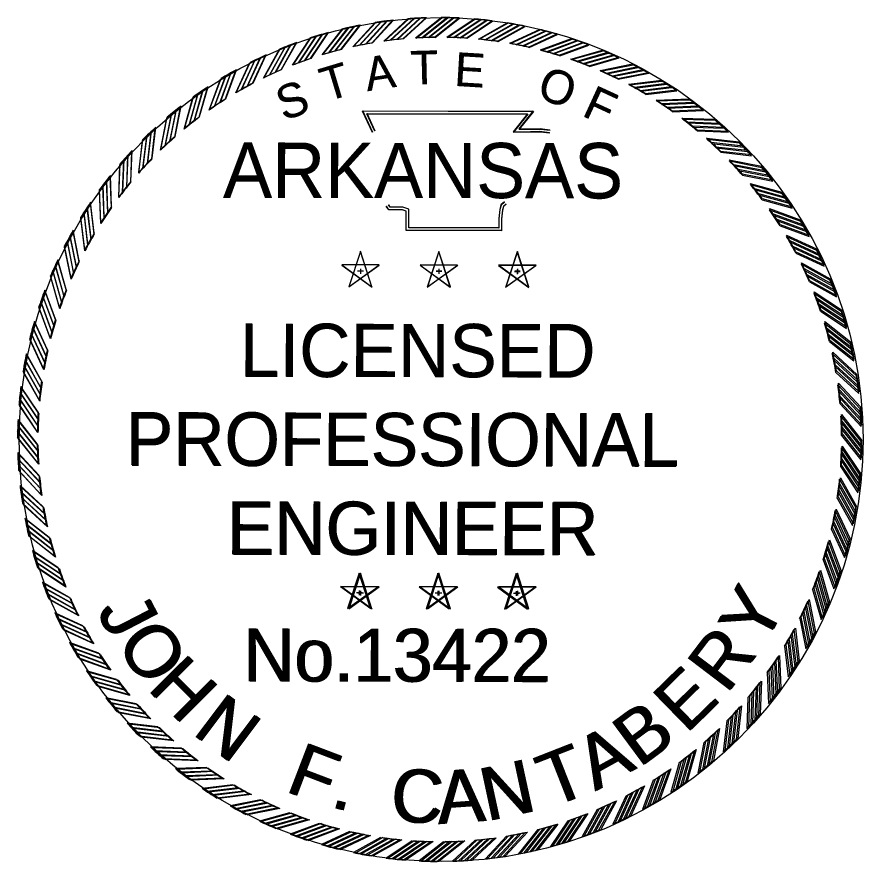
# Model space of a CAD drawing. Extents: x 0 to 762217, y -63 to 1662473.
# Drawn here: x 1782.1 to 1902.4, y 771.5 to 891.6 of the extents above; entities that cross this region are included whole.
import ezdxf

# ---------------------------------------------------------------- set-up
doc = ezdxf.new("R2010")
doc.units = 0
for name, color, linetype in [('Default', 7, 'Continuous'), ('G-ANNO-SYMB', 7, 'Continuous'), ('G-ANNO-TEXT', 7, 'Continuous'), ('G-No Plot-Stamp', 7, 'Continuous')]:
    doc.layers.add(name, color=color, linetype=linetype)

# ---------------------------------------------------------------- blocks, each defined once
blk = doc.blocks.new('STAR')
at = {"layer": 'Default'}
for p, q in [((-0.0001, 0.0615), (-0.0366, -0.0504)), ((0.0362, -0.0503), (0, 0.0617)), ((0.0587, 0.0188), (-0.059, 0.0189)), ((-0.0589, 0.0188), (0.0363, -0.0505)), ((-0.0365, -0.0503), (0.0589, 0.0188)), ((-0.0085, 0), (0.009, 0)), ((0, 0.0063), (0, -0.0085))]:
    blk.add_line(p, q, dxfattribs=at)
blk = doc.blocks.new('RP')
at = {"layer": 'Default'}
for p, q in [((-0.0781, 1.2656), (0.003, 1.33)), ((-0.058, 1.2667), (0.0216, 1.3299)), ((-0.0375, 1.2674), (0.0405, 1.3294)), ((-0.0176, 1.2679), (0.059, 1.3287))]:
    blk.add_line(p, q, dxfattribs=at)
for radius, start, end in [(1.33, 87.4562, 89.8699), (1.268, 90.7933, 93.5307)]:
    blk.add_arc((0, 0), radius, start, end, dxfattribs=at)

msp = doc.modelspace()

# ---------------------------------------------------------------- linework, layer by layer
at = {"layer": 'G-ANNO-SYMB'}
for points in [[(1832.61, 875.21), (1831.2, 878.24), (1855.46, 878.26), (1853.44, 875.71), (1855.09, 875.73), (1856.46, 875.75), (1857.84, 875.6)], [(1832.65, 875.22), (1831.26, 878.27), (1855.52, 878.2), (1853.49, 875.66), (1855.13, 875.67), (1856.51, 875.69), (1857.89, 875.53)], [(1832.96, 875.37), (1831.81, 877.86), (1854.67, 877.87), (1852.63, 875.32), (1855.09, 875.35), (1856.44, 875.37), (1857.8, 875.22)], [(1833, 875.38), (1831.86, 877.88), (1854.72, 877.81), (1852.68, 875.26), (1855.14, 875.29), (1856.49, 875.3), (1857.84, 875.15)], [(1851.4, 865.34), (1850.89, 864.92), (1850.71, 864.27), (1850.57, 862.96), (1850.57, 861.65), (1837.8, 861.65), (1837.8, 863.53), (1837.8, 864.32), (1836.92, 864.59), (1835.14, 864.59), (1834.91, 864.93)], [(1851.41, 865.29), (1850.9, 864.88), (1850.72, 864.23), (1850.57, 862.92), (1850.57, 861.61), (1837.8, 861.65), (1837.8, 863.53), (1837.81, 864.32), (1836.93, 864.59), (1835.15, 864.59), (1834.93, 864.94)], [(1851.64, 865.04), (1851.23, 864.7), (1851.09, 864.2), (1850.95, 862.94), (1850.95, 861.27), (1837.41, 861.27), (1837.41, 863.53), (1837.41, 864.03), (1836.86, 864.2), (1834.94, 864.2), (1834.59, 864.72)], [(1851.65, 864.99), (1851.24, 864.66), (1851.1, 864.15), (1850.96, 862.9), (1850.95, 861.22), (1837.41, 861.27), (1837.42, 863.53), (1837.42, 864.03), (1836.87, 864.2), (1834.95, 864.21), (1834.6, 864.73)]]:
    msp.add_lwpolyline(points, dxfattribs=at)
at = {"layer": 'G-No Plot-Stamp'}
msp.add_circle((1842.38, 831.54), 60, dxfattribs=at)

# ---------------------------------------------------------------- block references
at = {"layer": 'G-ANNO-SYMB'}
for name, p, xscale, yscale, rotation in [('RP', (1842.24, 831.56), 45.10357918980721, 45.10357918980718, 4.500000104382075), ('RP', (1842.24, 831.56), 45.103579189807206, 45.10357918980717, -4.499999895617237), ('RP', (1842.14, 831.54), 45.103579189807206, 45.10357918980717, -4.695800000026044), ('RP', (1842.24, 831.56), 45.10357918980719, 45.10357918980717, 13.500000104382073), ('RP', (1842.14, 831.54), 45.1035791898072, 45.103579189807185, 13.304199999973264), ('RP', (1842.24, 831.56), 45.103579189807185, 45.103579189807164, 9.000000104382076), ('RP', (1842.14, 831.54), 45.10357918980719, 45.103579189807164, 8.804199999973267), ('RP', (1842.14, 831.54), 45.1035791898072, 45.10357918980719, 4.304199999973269), ('RP', (1842.24, 831.56), 45.1035791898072, 45.10357918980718, 1.0438208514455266e-07), ('RP', (1842.14, 831.54), 45.1035791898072, 45.10357918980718, -0.19580000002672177), ('RP', (1842.24, 831.56), 45.10357918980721, 45.103579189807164, -8.999999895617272), ('RP', (1842.14, 831.54), 45.10357918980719, 45.103579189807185, -9.19580000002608), ('RP', (1842.24, 831.56), 45.10357918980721, 45.10357918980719, -13.499999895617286), ('RP', (1842.14, 831.54), 45.103579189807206, 45.103579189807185, -13.695800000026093), ('RP', (1842.24, 831.56), 45.103579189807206, 45.10357918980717, 18.00000010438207), ('RP', (1842.14, 831.54), 45.1035791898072, 45.10357918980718, 17.804199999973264), ('RP', (1842.24, 831.56), 45.103579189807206, 45.103579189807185, -17.999999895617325), ('RP', (1842.14, 831.54), 45.1035791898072, 45.10357918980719, -18.19580000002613), ('RP', (1842.24, 831.56), 45.1035791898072, 45.10357918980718, 22.500000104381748), ('RP', (1842.14, 831.54), 45.1035791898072, 45.10357918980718, 22.304199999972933), ('RP', (1842.24, 831.56), 45.103579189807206, 45.10357918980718, -22.499999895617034), ('RP', (1842.14, 831.54), 45.10357918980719, 45.103579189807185, -22.695800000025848), ('RP', (1842.24, 831.56), 45.1035791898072, 45.10357918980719, 27.000000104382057), ('RP', (1842.14, 831.54), 45.1035791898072, 45.103579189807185, 26.80419999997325), ('RP', (1842.24, 831.56), 45.10357918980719, 45.103579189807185, -26.999999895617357), ('RP', (1842.14, 831.54), 45.1035791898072, 45.10357918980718, -27.19580000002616), ('RP', (1842.24, 831.56), 45.10357918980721, 45.1035791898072, -31.49999989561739), ('RP', (1842.14, 831.54), 45.103579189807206, 45.1035791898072, -31.695800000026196), ('RP', (1842.24, 831.56), 45.10357918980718, 45.103579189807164, 31.50000010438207), ('RP', (1842.14, 831.54), 45.10357918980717, 45.103579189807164, 31.30419999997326), ('RP', (1842.24, 831.56), 45.10357918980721, 45.10357918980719, -35.999999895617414), ('RP', (1842.14, 831.54), 45.1035791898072, 45.10357918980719, -36.195800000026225), ('RP', (1842.24, 831.56), 45.10357918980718, 45.103579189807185, 36.00000010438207), ('RP', (1842.14, 831.54), 45.10357918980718, 45.10357918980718, 35.804199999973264), ('RP', (1842.24, 831.56), 45.103579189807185, 45.10357918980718, 40.50000010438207), ('RP', (1842.14, 831.54), 45.103579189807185, 45.10357918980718, 40.30419999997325), ('RP', (1842.24, 831.56), 45.1035791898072, 45.1035791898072, -40.49999989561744), ('RP', (1842.14, 831.54), 45.1035791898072, 45.10357918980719, -40.69580000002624), ('RP', (1842.14, 831.54), 45.103579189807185, 45.10357918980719, 44.80419999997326), ('RP', (1842.24, 831.56), 45.1035791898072, 45.10357918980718, -44.99999989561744), ('RP', (1842.14, 831.54), 45.103579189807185, 45.10357918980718, -45.19580000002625), ('RP', (1842.24, 831.56), 45.10357918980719, 45.10357918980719, 45.00000010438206), ('RP', (1842.24, 831.56), 45.10357918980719, 45.103579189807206, 49.500000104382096), ('RP', (1842.14, 831.54), 45.103579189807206, 45.1035791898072, 49.304199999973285), ('RP', (1842.24, 831.56), 45.103579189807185, 45.10357918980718, -49.499999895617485), ('RP', (1842.14, 831.54), 45.10357918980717, 45.103579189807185, -49.695800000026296), ('RP', (1842.24, 831.56), 45.103579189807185, 45.10357918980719, 54.00000010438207), ('RP', (1842.14, 831.54), 45.10357918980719, 45.103579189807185, 53.804199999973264), ('RP', (1842.24, 831.56), 45.10357918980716, 45.10357918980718, -53.999999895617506), ('RP', (1842.14, 831.54), 45.103579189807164, 45.10357918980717, -54.1958000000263), ('RP', (1842.14, 831.54), 45.10357918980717, 45.103579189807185, 58.304199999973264), ('RP', (1842.24, 831.56), 45.10357918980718, 45.10357918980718, 58.50000010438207), ('RP', (1842.24, 831.56), 45.103579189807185, 45.10357918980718, -58.49999989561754), ('RP', (1842.14, 831.54), 45.10357918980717, 45.103579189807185, -58.695800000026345), ('RP', (1842.24, 831.56), 45.10357918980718, 45.10357918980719, -62.99999989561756), ('RP', (1842.14, 831.54), 45.103579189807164, 45.10357918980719, -63.19580000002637), ('RP', (1842.14, 831.54), 45.103579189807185, 45.103579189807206, 62.804199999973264), ('RP', (1842.24, 831.56), 45.10357918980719, 45.1035791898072, 63.000000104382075), ('STAR', (1830.9, 855.53), 45.1035791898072, 45.10357918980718, -0.19580000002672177), ('STAR', (1830.92, 855.51), 45.1035791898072, 45.10357918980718, 1.0438208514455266e-07), ('STAR', (1842.06, 855.49), 45.1035791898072, 45.10357918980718, -0.19580000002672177), ('STAR', (1842.08, 855.51), 45.1035791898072, 45.10357918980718, 1.0438208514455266e-07), ('STAR', (1853.21, 855.45), 45.1035791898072, 45.10357918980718, -0.19580000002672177), ('STAR', (1853.23, 855.51), 45.1035791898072, 45.10357918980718, 1.0438208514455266e-07), ('RP', (1842.14, 831.54), 45.10357918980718, 45.1035791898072, 67.30419999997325), ('RP', (1842.24, 831.56), 45.10357918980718, 45.103579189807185, 67.50000010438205), ('RP', (1842.14, 831.54), 45.10357918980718, 45.103579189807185, -67.69580000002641), ('RP', (1842.24, 831.56), 45.10357918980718, 45.1035791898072, -67.49999989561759), ('RP', (1842.14, 831.54), 45.10357918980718, 45.1035791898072, -72.19580000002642), ('RP', (1842.24, 831.56), 45.10357918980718, 45.1035791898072, -71.99999989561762), ('RP', (1842.14, 831.54), 45.103579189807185, 45.1035791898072, 71.80419999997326), ('RP', (1842.24, 831.56), 45.103579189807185, 45.10357918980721, 72.00000010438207), ('RP', (1842.14, 831.54), 45.10357918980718, 45.1035791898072, 76.30419999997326), ('RP', (1842.14, 831.54), 45.10357918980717, 45.10357918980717, -76.69580000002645), ('RP', (1842.24, 831.56), 45.103579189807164, 45.10357918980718, -76.49999989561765), ('RP', (1842.24, 831.56), 45.103579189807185, 45.103579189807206, 76.50000010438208), ('RP', (1842.14, 831.54), 45.10357918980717, 45.10357918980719, 80.80419999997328), ('RP', (1842.24, 831.56), 45.10357918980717, 45.10357918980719, 81.0000001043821), ('RP', (1842.14, 831.54), 45.10357918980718, 45.1035791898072, -81.19580000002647), ('RP', (1842.24, 831.56), 45.10357918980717, 45.1035791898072, -80.99999989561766), ('RP', (1842.14, 831.54), 45.10357918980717, 45.10357918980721, 85.30419999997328), ('RP', (1842.24, 831.56), 45.10357918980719, 45.1035791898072, 85.50000010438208), ('RP', (1842.14, 831.54), 45.103579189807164, 45.10357918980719, -85.69580000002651), ('RP', (1842.24, 831.56), 45.10357918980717, 45.103579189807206, -85.49999989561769), ('RP', (1842.24, 831.56), 45.10357918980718, 45.10357918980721, -89.99999989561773), ('RP', (1842.14, 831.54), 45.10357918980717, 45.103579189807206, 89.80419999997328), ('RP', (1842.24, 831.56), 45.103579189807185, 45.10357918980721, 90.0000001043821), ('RP', (1842.14, 831.54), 45.10357918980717, 45.103579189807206, -90.19580000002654), ('RP', (1842.14, 831.54), 45.10357918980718, 45.103579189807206, -94.69580000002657), ('RP', (1842.24, 831.56), 45.103579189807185, 45.10357918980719, -94.49999989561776), ('RP', (1842.14, 831.54), 45.10357918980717, 45.10357918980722, 94.30419999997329), ('RP', (1842.24, 831.56), 45.103579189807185, 45.10357918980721, 94.5000001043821), ('RP', (1842.14, 831.54), 45.10357918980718, 45.10357918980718, 98.8041999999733), ('RP', (1842.14, 831.54), 45.10357918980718, 45.1035791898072, -99.19580000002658), ('RP', (1842.24, 831.56), 45.10357918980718, 45.1035791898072, -98.99999989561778), ('RP', (1842.24, 831.56), 45.10357918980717, 45.103579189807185, 99.0000001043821), ('RP', (1842.14, 831.54), 45.10357918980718, 45.1035791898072, 103.30419999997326), ('RP', (1842.24, 831.56), 45.10357918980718, 45.1035791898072, 103.50000010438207), ('RP', (1842.14, 831.54), 45.10357918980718, 45.1035791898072, -103.69580000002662), ('RP', (1842.24, 831.56), 45.10357918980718, 45.10357918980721, -103.49999989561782), ('RP', (1842.14, 831.54), 45.10357918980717, 45.1035791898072, -108.19580000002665), ('RP', (1842.24, 831.56), 45.10357918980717, 45.1035791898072, -107.99999989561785), ('RP', (1842.14, 831.54), 45.10357918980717, 45.10357918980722, 107.80419999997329), ('RP', (1842.24, 831.56), 45.10357918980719, 45.10357918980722, 108.0000001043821), ('RP', (1842.14, 831.54), 45.10357918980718, 45.103579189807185, 112.30419999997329), ('RP', (1842.24, 831.56), 45.10357918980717, 45.1035791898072, 112.5000001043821), ('STAR', (1830.74, 809.78), 45.1035791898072, 45.10357918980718, -0.19580000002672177), ('STAR', (1830.92, 809.76), 45.1035791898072, 45.10357918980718, 1.0438208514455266e-07), ('STAR', (1841.9, 809.74), 45.1035791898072, 45.10357918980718, -0.19580000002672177), ('STAR', (1842.08, 809.76), 45.1035791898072, 45.10357918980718, 1.0438208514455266e-07), ('STAR', (1853.06, 809.7), 45.1035791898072, 45.10357918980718, -0.19580000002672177), ('STAR', (1853.23, 809.76), 45.1035791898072, 45.10357918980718, 1.0438208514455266e-07), ('RP', (1842.14, 831.54), 45.10357918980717, 45.103579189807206, -112.69580000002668), ('RP', (1842.24, 831.56), 45.10357918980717, 45.10357918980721, -112.49999989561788), ('RP', (1842.14, 831.54), 45.10357918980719, 45.103579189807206, -117.19580000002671), ('RP', (1842.24, 831.56), 45.1035791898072, 45.103579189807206, -116.9999998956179), ('RP', (1842.14, 831.54), 45.103579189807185, 45.1035791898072, 116.80419999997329), ('RP', (1842.24, 831.56), 45.10357918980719, 45.1035791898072, 117.0000001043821), ('RP', (1842.14, 831.54), 45.103579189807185, 45.103579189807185, 121.30419999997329), ('RP', (1842.24, 831.56), 45.103579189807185, 45.10357918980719, 121.5000001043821), ('RP', (1842.14, 831.54), 45.10357918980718, 45.103579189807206, -121.69580000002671), ('RP', (1842.24, 831.56), 45.10357918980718, 45.103579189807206, -121.4999998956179), ('RP', (1842.14, 831.54), 45.10357918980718, 45.10357918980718, 125.80419999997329), ('RP', (1842.24, 831.56), 45.10357918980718, 45.103579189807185, 126.00000010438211), ('RP', (1842.14, 831.54), 45.10357918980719, 45.1035791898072, -126.19580000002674), ('RP', (1842.24, 831.56), 45.103579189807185, 45.103579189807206, -125.99999989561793), ('RP', (1842.14, 831.54), 45.10357918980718, 45.103579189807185, 130.3041999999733), ('RP', (1842.14, 831.54), 45.103579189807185, 45.10357918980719, -130.6958000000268), ('RP', (1842.24, 831.56), 45.103579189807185, 45.10357918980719, -130.49999989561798), ('RP', (1842.24, 831.56), 45.103579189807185, 45.10357918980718, 130.50000010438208), ('RP', (1842.14, 831.54), 45.10357918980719, 45.103579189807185, 134.80419999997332), ('RP', (1842.24, 831.56), 45.1035791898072, 45.103579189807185, 135.00000010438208), ('RP', (1842.14, 831.54), 45.103579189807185, 45.10357918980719, -135.19580000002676), ('RP', (1842.24, 831.56), 45.10357918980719, 45.10357918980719, -134.99999989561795), ('RP', (1842.14, 831.54), 45.10357918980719, 45.103579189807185, 139.30419999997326), ('RP', (1842.24, 831.56), 45.10357918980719, 45.103579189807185, 139.50000010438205), ('RP', (1842.14, 831.54), 45.10357918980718, 45.103579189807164, -139.69580000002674), ('RP', (1842.24, 831.56), 45.103579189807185, 45.10357918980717, -139.49999989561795), ('RP', (1842.14, 831.54), 45.103579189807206, 45.103579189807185, 143.8041999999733), ('RP', (1842.24, 831.56), 45.103579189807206, 45.103579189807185, 144.00000010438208), ('RP', (1842.14, 831.54), 45.103579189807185, 45.103579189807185, -144.19580000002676), ('RP', (1842.24, 831.56), 45.1035791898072, 45.10357918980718, -143.99999989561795), ('RP', (1842.14, 831.54), 45.10357918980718, 45.10357918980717, -148.69580000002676), ('RP', (1842.24, 831.56), 45.10357918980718, 45.103579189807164, -148.49999989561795), ('RP', (1842.14, 831.54), 45.10357918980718, 45.10357918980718, 148.3041999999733), ('RP', (1842.24, 831.56), 45.103579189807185, 45.10357918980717, 148.50000010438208), ('RP', (1842.14, 831.54), 45.103579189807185, 45.10357918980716, -153.1958000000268), ('RP', (1842.24, 831.56), 45.10357918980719, 45.103579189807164, -152.99999989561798), ('RP', (1842.14, 831.54), 45.10357918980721, 45.103579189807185, 152.8041999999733), ('RP', (1842.24, 831.56), 45.10357918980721, 45.1035791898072, 153.00000010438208), ('RP', (1842.14, 831.54), 45.1035791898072, 45.10357918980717, 157.3041999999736), ('RP', (1842.24, 831.56), 45.103579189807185, 45.10357918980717, 157.50000010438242), ('RP', (1842.14, 831.54), 45.1035791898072, 45.103579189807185, -157.6958000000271), ('RP', (1842.24, 831.56), 45.10357918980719, 45.10357918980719, -157.4999998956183), ('RP', (1842.14, 831.54), 45.103579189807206, 45.10357918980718, 161.8041999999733), ('RP', (1842.24, 831.56), 45.10357918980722, 45.103579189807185, 162.00000010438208), ('RP', (1842.14, 831.54), 45.1035791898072, 45.10357918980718, -162.19580000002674), ('RP', (1842.24, 831.56), 45.103579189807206, 45.103579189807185, -161.99999989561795), ('RP', (1842.14, 831.54), 45.103579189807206, 45.10357918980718, 166.3041999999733), ('RP', (1842.24, 831.56), 45.103579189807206, 45.10357918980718, 166.50000010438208), ('RP', (1842.14, 831.54), 45.1035791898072, 45.10357918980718, -166.69580000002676), ('RP', (1842.24, 831.56), 45.10357918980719, 45.103579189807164, -166.49999989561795), ('RP', (1842.14, 831.54), 45.1035791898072, 45.10357918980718, 170.8041999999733), ('RP', (1842.24, 831.56), 45.1035791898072, 45.10357918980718, 171.00000010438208), ('RP', (1842.14, 831.54), 45.103579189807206, 45.10357918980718, 175.3041999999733), ('RP', (1842.24, 831.56), 45.10357918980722, 45.10357918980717, 175.50000010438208), ('RP', (1842.14, 831.54), 45.10357918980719, 45.103579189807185, -175.69580000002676), ('RP', (1842.24, 831.56), 45.1035791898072, 45.10357918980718, -175.49999989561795), ('RP', (1842.14, 831.54), 45.10357918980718, 45.10357918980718, -171.19580000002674), ('RP', (1842.24, 831.56), 45.103579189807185, 45.103579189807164, -170.99999989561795), ('RP', (1842.14, 831.54), 45.1035791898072, 45.10357918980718, 179.8041999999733), ('RP', (1842.24, 831.56), 45.10357918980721, 45.103579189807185, -179.99999989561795)]:
    msp.add_blockref(name, p, dxfattribs=dict(at, xscale=xscale, yscale=yscale, rotation=rotation))

# ---------------------------------------------------------------- texts
at = {"layer": 'G-ANNO-TEXT'}
for s, height, rotation, p in [('T', 4.79, 1.4789, (1838.05, 882)), ('T', 4.79, 1.2831, (1838.12, 882)), ('A', 4.79, 8.6788, (1831.87, 881.05)), ('A', 4.79, 8.483, (1831.93, 881.07)), ('E', 4.79, 356.672, (1844.17, 881.85)), ('E', 4.79, 356.4762, (1844.24, 881.83)), ('T', 4.79, 16.9015, (1826.06, 879.53)), ('T', 4.79, 16.7057, (1826.12, 879.57)), ('O', 4.79, 341.2218, (1855.79, 880.21)), ('O', 4.79, 341.026, (1855.86, 880.15)), ('S', 4.79, 19.7726, (1819.97, 876.8)), ('S', 4.79, 19.5768, (1820.02, 876.86)), ('F', 4.79, 335.3628, (1862.24, 877.69)), ('F', 4.79, 335.167, (1862.3, 877.61)), ('ARKANSAS', 7.81, 0, (1811.37, 865.91)), ('ARKANSAS', 7.81, 359.8042, (1811.39, 866)), ('LICENSED', 7.561, 359.8042, (1813.73, 840.5)), ('LICENSED', 7.561, 0, (1813.8, 840.42)), ('PROFESSIONAL', 7.5612, 359.8042, (1797.48, 827.91)), ('PROFESSIONAL', 7.5612, 0, (1797.6, 827.77)), ('ENGINEER', 7.561, 359.8042, (1811.84, 815.22)), ('ENGINEER', 7.561, 0, (1812, 815.13)), ('Y', 7.56, 62.5392, (1888.23, 801.86)), ('Y', 7.56, 62.735, (1888.44, 802.04)), ('J', 7.56, 297.2813, (1793.27, 807.24)), ('J', 7.56, 297.4771, (1793.45, 807.09)), ('O', 7.56, 304.1899, (1795.94, 802.6)), ('O', 7.56, 304.3857, (1796.15, 802.46)), ('No.13422', 7.531, 359.8042, (1814.17, 797.18)), ('No.13422', 7.531, 0, (1814.38, 797.11)), ('R', 7.56, 52.7437, (1882.96, 795.21)), ('R', 7.56, 52.9395, (1883.18, 795.36)), ('H', 7.56, 314.7447, (1800.41, 796.09)), ('H', 7.56, 314.9405, (1800.63, 795.96)), ('E', 7.56, 44.306, (1877.2, 789.58)), ('E', 7.56, 44.5018, (1877.44, 789.71)), ('N', 7.56, 322.9417, (1806.79, 789.76)), ('N', 7.56, 323.1375, (1807.03, 789.66)), ('B', 7.56, 36.505, (1870.52, 784.77)), ('B', 7.56, 36.7008, (1870.78, 784.88)), ('A', 7.56, 28.8562, (1864.24, 781.47)), ('A', 7.56, 29.052, (1864.52, 781.56)), ('F', 7.56, 339.0288, (1819.99, 781.57)), ('F', 7.56, 339.2246, (1820.26, 781.52)), ('T', 7.56, 21.4329, (1857.96, 779.1)), ('T', 7.56, 21.6287, (1858.24, 779.17)), ('N', 7.56, 12.0703, (1848.84, 777.22)), ('N', 7.56, 12.2661, (1849.12, 777.26)), ('C', 7.56, 356.1028, (1834.99, 777.33)), ('C', 7.56, 356.2986, (1835.28, 777.32)), ('A', 7.56, 3.9092, (1841.92, 776.83)), ('A', 7.56, 4.105, (1842.21, 776.85)), ('.', 7.56, 344.7037, (1826.44, 779.34)), ('.', 7.56, 344.8995, (1826.72, 779.3))]:
    msp.add_text(s, height=height, rotation=rotation, dxfattribs=at).set_placement(p)

doc.saveas('drawing.dxf')
